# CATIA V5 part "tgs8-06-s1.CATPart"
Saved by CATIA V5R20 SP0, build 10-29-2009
Part number: TGS8-06-S1
Revision: 1
Definition: design
Nomenclature: TGS8-06-S1
Source: made
Description: NOT SPECIFIED
Bounding box of the stored display mesh (mm): x -3 to 3, y -8 to 0, z -22 to 0.6
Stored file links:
  C:\Users\Raffaele\Desktop\3D X SITO CF\I-MOLD\TGS-S1\tgs8-s1.step\tgs8-06-s1.CATPart
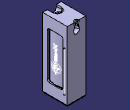
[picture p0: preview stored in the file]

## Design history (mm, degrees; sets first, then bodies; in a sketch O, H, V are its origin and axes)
Set1
  DatumCurve1 "COMPOSITE_CURVE #4117"
  DatumCurve2 "COMPOSITE_CURVE #4163"
  DatumCurve3 "COMPOSITE_CURVE #4396"
  DatumCurve4 "COMPOSITE_CURVE #4456"
  DatumCurve5 "COMPOSITE_CURVE #4513"
  DatumCurve6 "COMPOSITE_CURVE #4674"
  DatumCurve7 "COMPOSITE_CURVE #4701"
  DatumCurve8 "COMPOSITE_CURVE #4728"
  DatumCurve9 "COMPOSITE_CURVE #4811"
  DatumCurve10 "COMPOSITE_CURVE #4862"
  Line1 "LINE #4866": stored without definition
  DatumSurface1 "OPEN_SHELL #3969"
  DatumSurface2 "OPEN_SHELL #4066"
Body1 "MANIFOLD_SOLID_BREP #4067" (main body)
  Solid1: solid without history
